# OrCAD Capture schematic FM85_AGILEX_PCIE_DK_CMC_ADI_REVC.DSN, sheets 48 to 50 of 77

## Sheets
48 LEDs, PushButton And IOEXP: size B
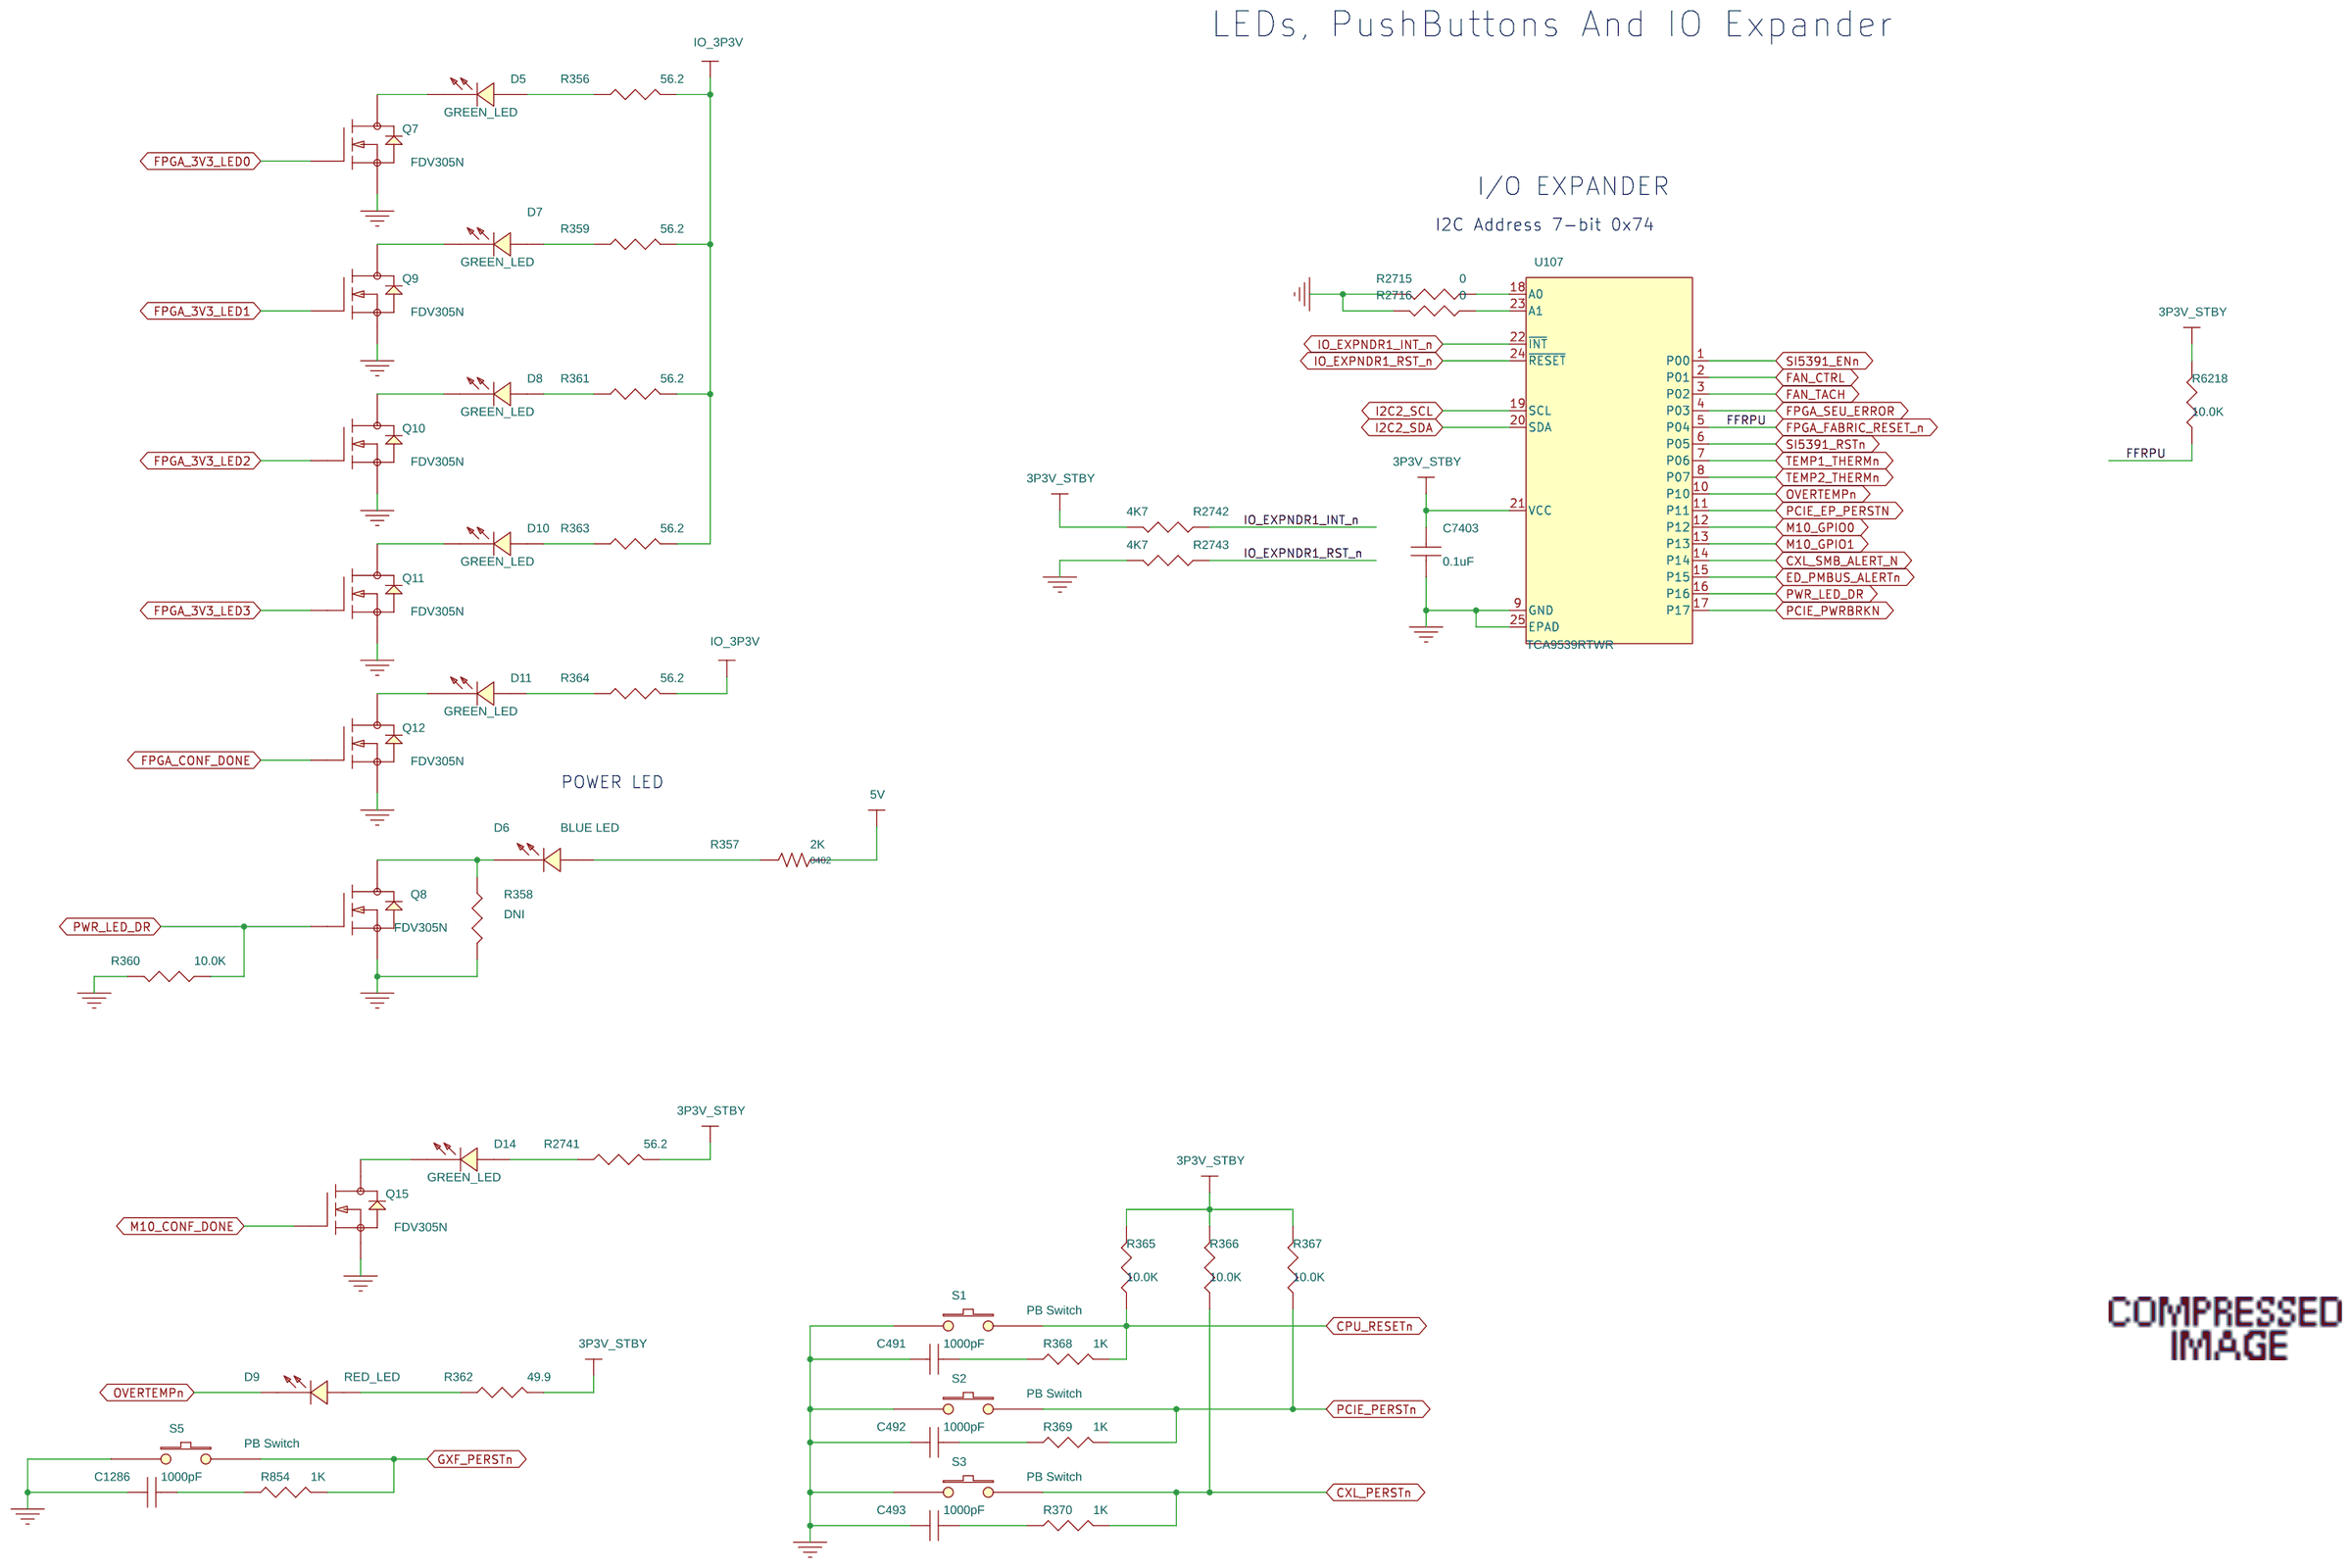
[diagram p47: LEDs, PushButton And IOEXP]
49 System MAX10 1: size B
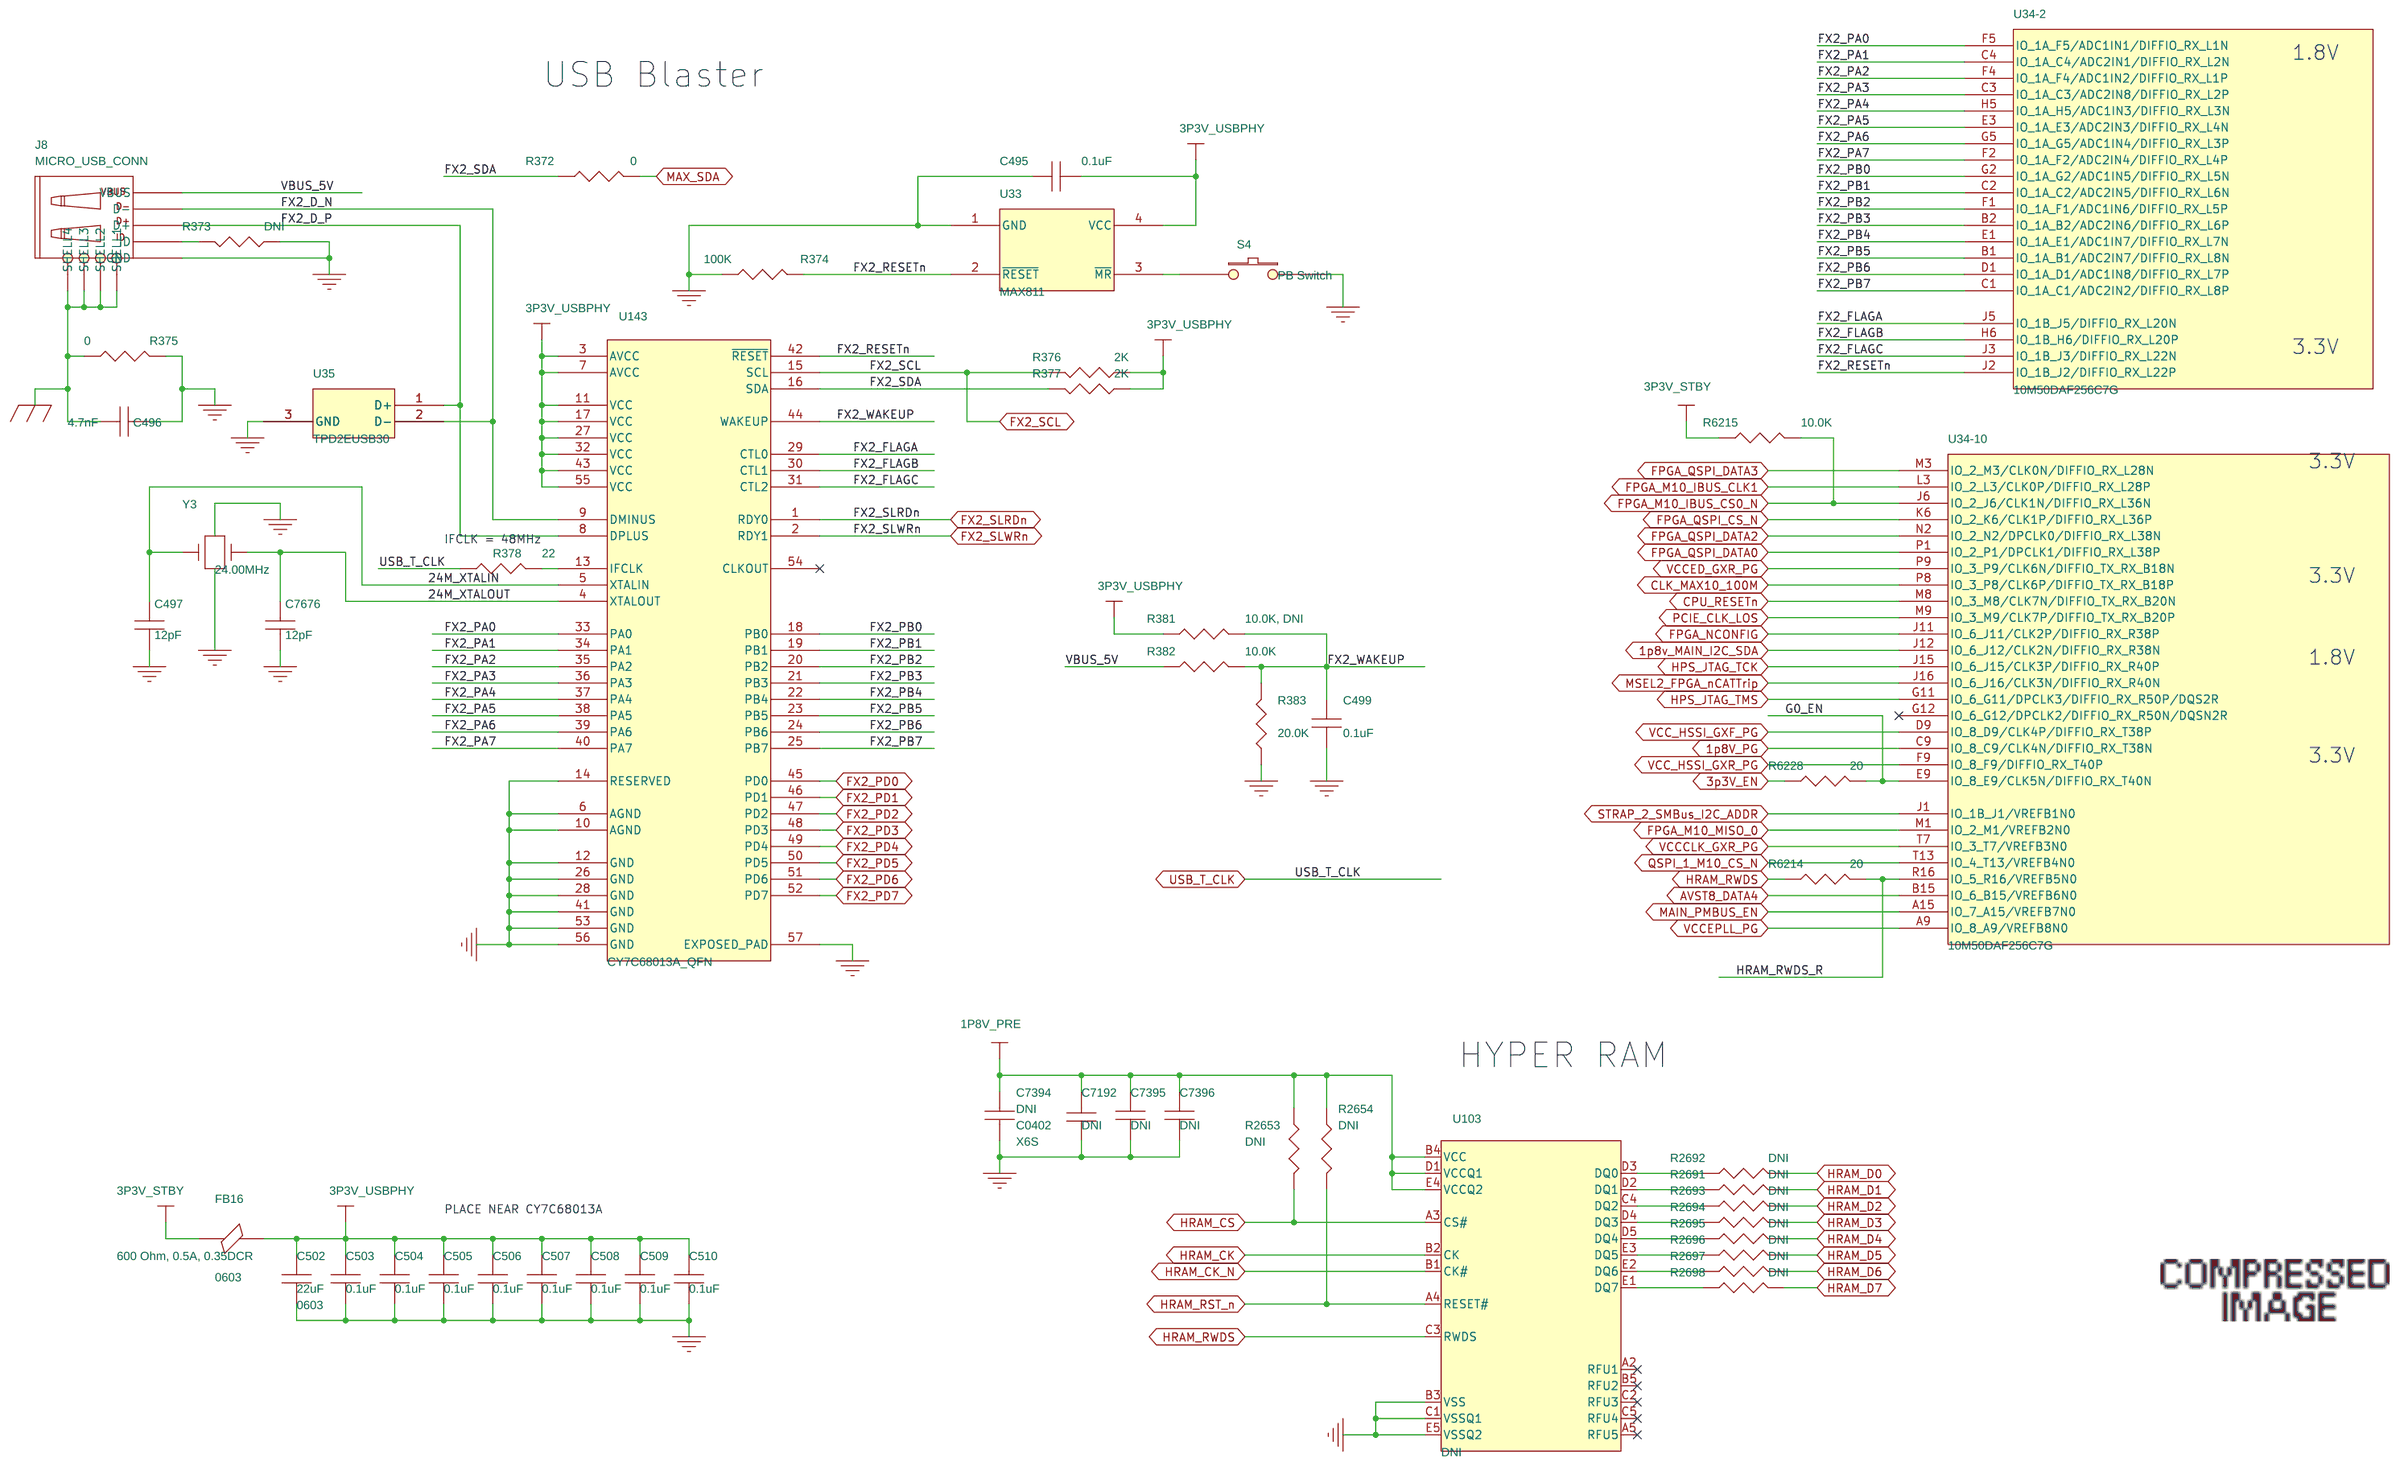
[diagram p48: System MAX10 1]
50 System MAX10 2: size B
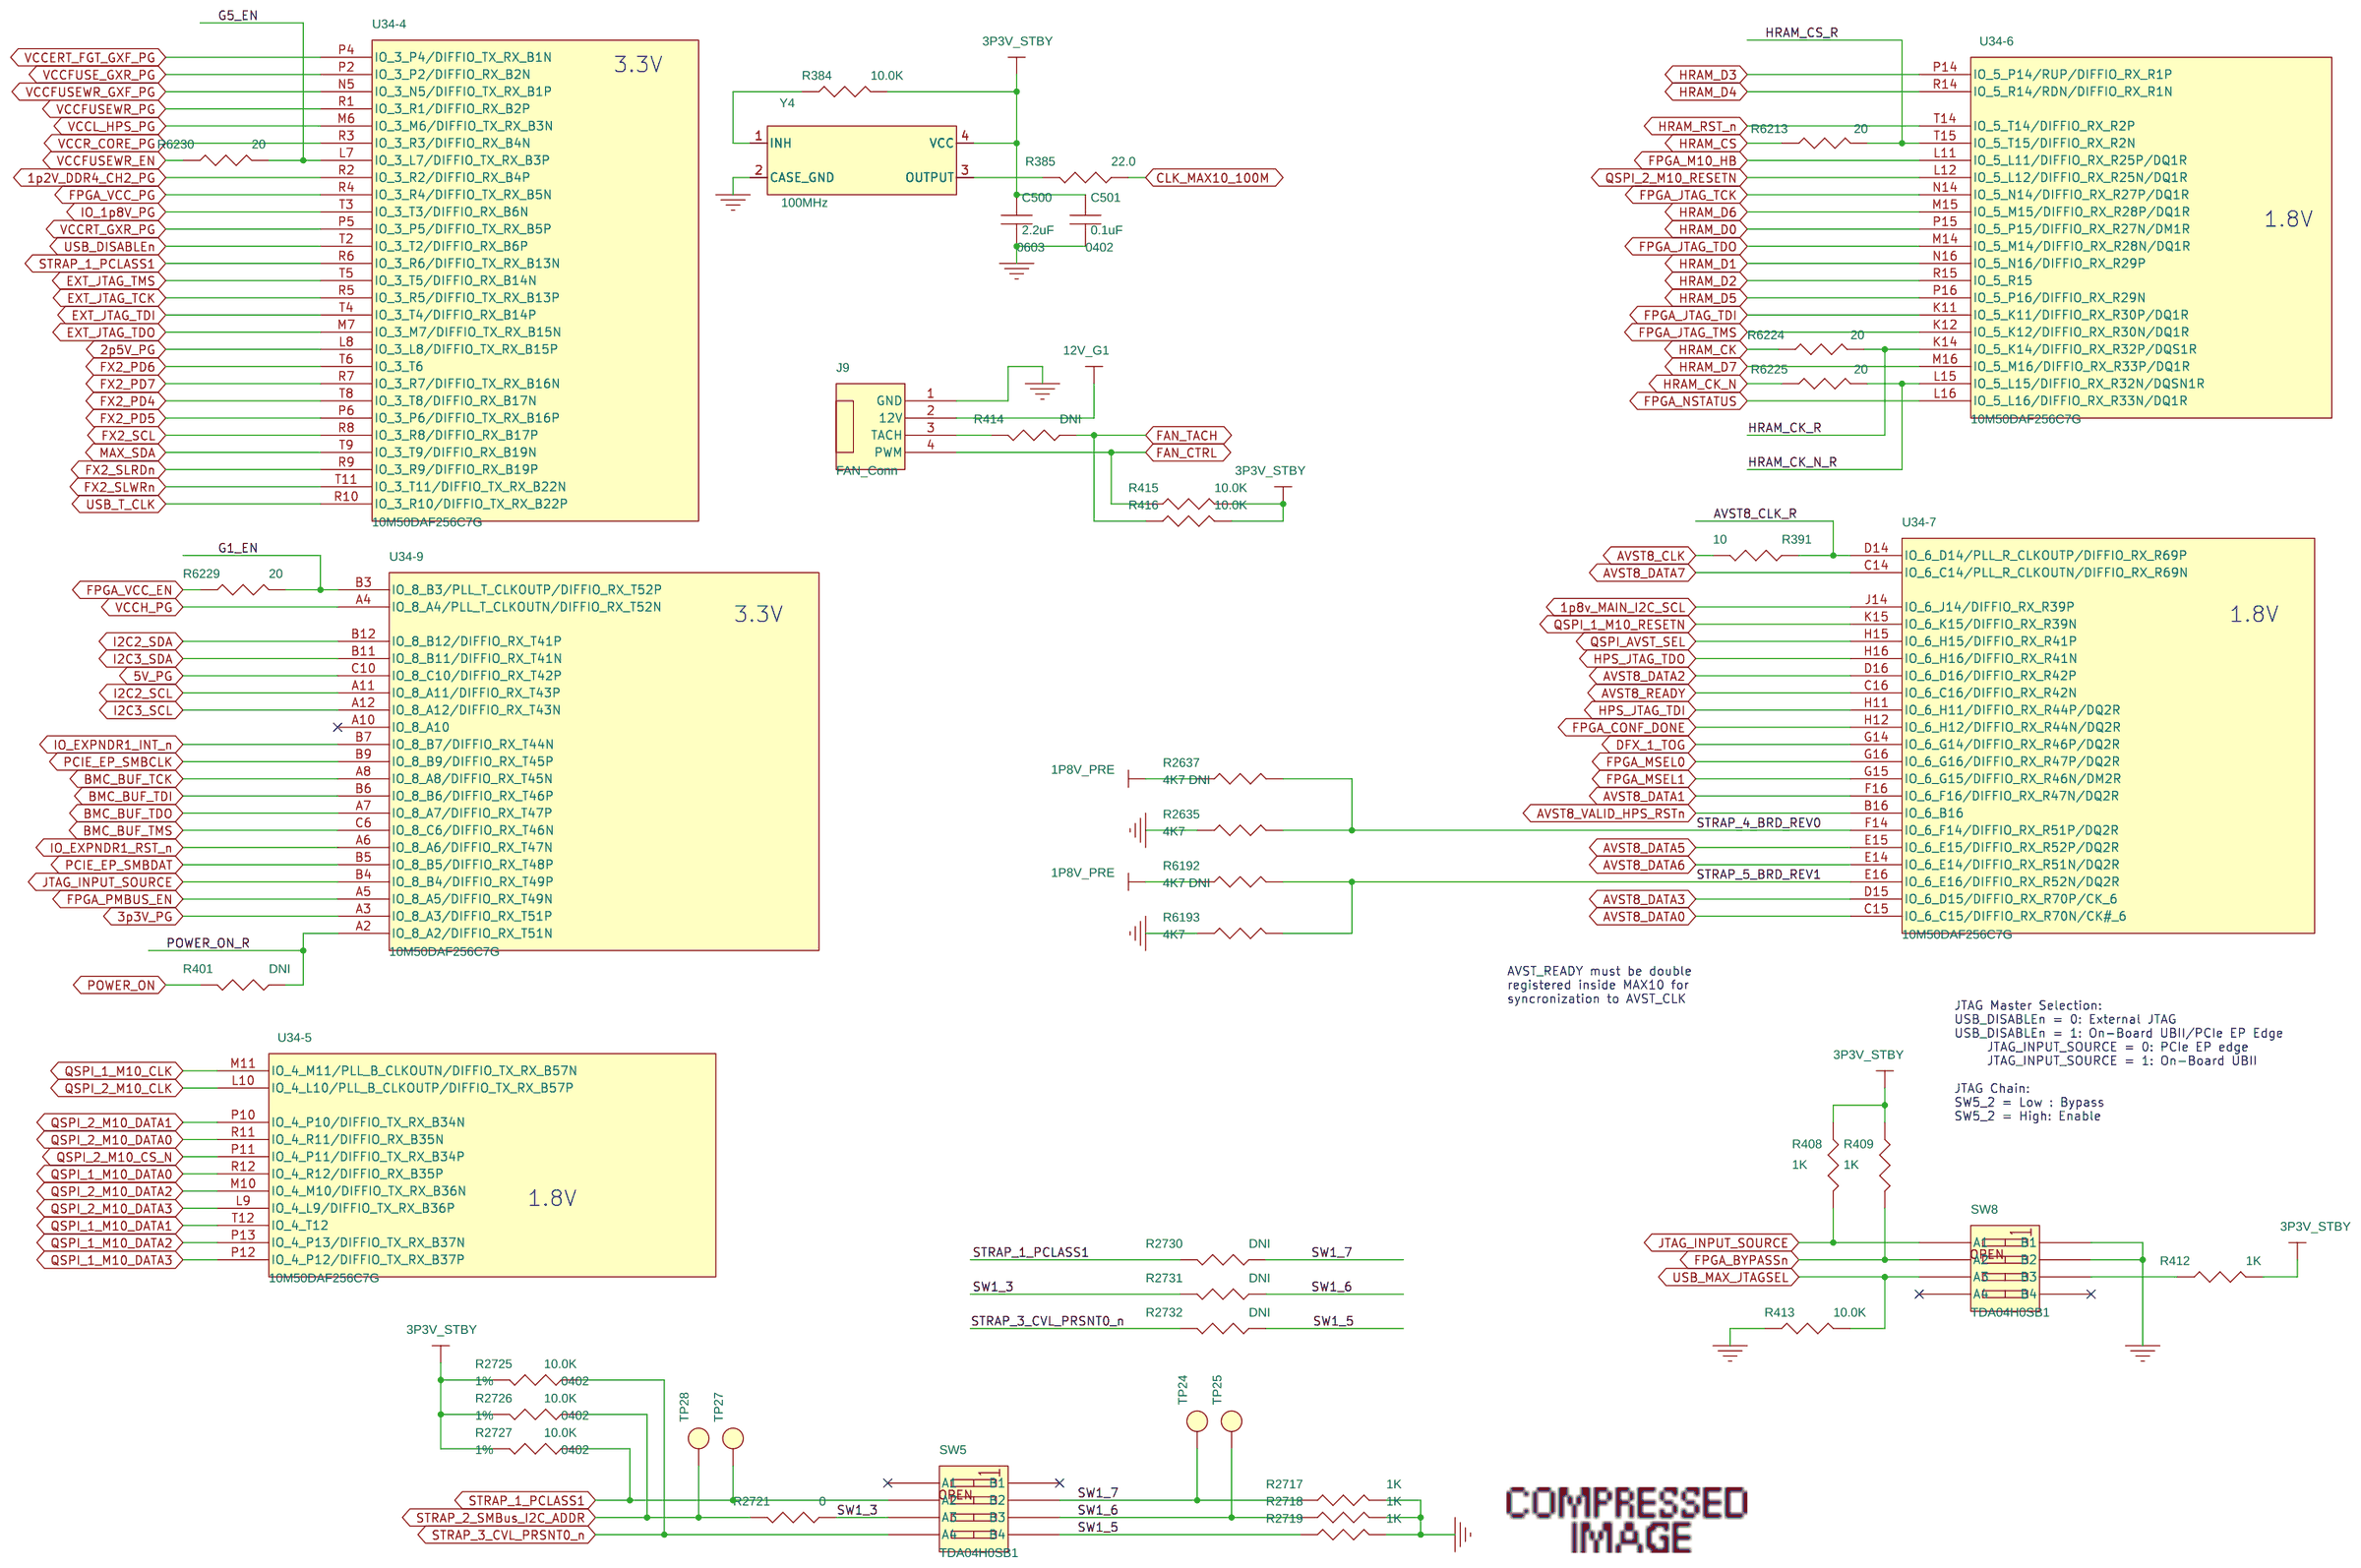
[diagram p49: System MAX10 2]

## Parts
sheet LEDs, PushButton And IOEXP
C491  1000pF  [0402]
C492  1000pF  [0402]
C493  1000pF  [0402]
C1286  1000pF  [0402]
C7403  0.1uF  [0402]
D5  GREEN_LED  [LED_0603]
D6  BLUE LED  [LED_0603]
D7  GREEN_LED  [LED_0603]
D8  GREEN_LED  [LED_0603]
D9  RED_LED  [LED_0603]
D10  GREEN_LED  [LED_0603]
D11  GREEN_LED  [LED_0603]
D14  GREEN_LED  [LED_0603]
Q7  FDV305N  [SOT23]
Q8  FDV305N  [SOT23]
Q9  FDV305N  [SOT23]
Q10  FDV305N  [SOT23]
Q11  FDV305N  [SOT23]
Q12  FDV305N  [SOT23]
Q15  FDV305N  [SOT23]
R356  56.2  [0402]
R357  2K  [0402]
R358  DNI  [0402]
R359  56.2  [0402]
R360  10.0K  [0402]
R361  56.2  [0402]
R362  49.9  [0402]
R363  56.2  [0402]
R364  56.2  [0402]
R365  10.0K  [0402]
R366  10.0K  [0402]
R367  10.0K  [0402]
R368  1K  [0402]
R369  1K  [0402]
R370  1K  [0402]
R854  1K  [0402]
R2715  0  [0402]
R2716  0  [0402]
R2741  56.2  [0402]
R2742  4K7  [0201]
R2743  4K7  [0201]
R6218  10.0K  [0402]
S1  PB Switch  [WURTH_6X3P5_TACT_SWITCH]
S2  PB Switch  [WURTH_6X3P5_TACT_SWITCH]
S3  PB Switch  [WURTH_6X3P5_TACT_SWITCH]
S5  PB Switch  [WURTH_6X3P5_TACT_SWITCH]
U107  TCA9539RTWR  [qfn50p410x410x80-25-cust]
sheet System MAX10 1
C495  0.1uF  [0402]
C496  4.7nF  [0402]
C497  12pF  [0402]
C499  0.1uF  [0402]
C502  22uF  [0603]
C503  0.1uF  [0402]
C504  0.1uF  [0402]
C505  0.1uF  [0402]
C506  0.1uF  [0402]
C507  0.1uF  [0402]
C508  0.1uF  [0402]
C509  0.1uF  [0402]
C510  0.1uF  [0402]
C7192  DNI  [C0402]
C7394  DNI  [C0402]
C7395  DNI  [C0402]
C7396  DNI  [C0402]
C7676  12pF  [0402]
FB16  600 Ohm, 0.5A, 0.35DCR  [0603]
J8  MICRO_USB_CONN  [molex-micro-usb-47589-001]
R372  0  [0402]
R373  DNI  [0402]
R374  100K  [0402]
R375  0  [0402]
R376  2K  [0402]
R377  2K  [0402]
R378  22  [0402]
R381  10.0K, DNI  [0402]
R382  10.0K  [0402]
R383  20.0K  [0402]
R2653  DNI  [0201]
R2654  DNI  [0201]
R2691  DNI  [0201]
R2692  DNI  [0201]
R2693  DNI  [0201]
R2694  DNI  [0201]
R2695  DNI  [0201]
R2696  DNI  [0201]
R2697  DNI  [0201]
R2698  DNI  [0201]
R6214  20  [0402]
R6215  10.0K  [0402]
R6228  20  [0402]
S4  PB Switch  [WURTH_6X3P5_TACT_SWITCH]
U33  MAX811  [SOT-143]
U35  TPD2EUSB30  [DRT]
U103  DNI  [TFBGA24]
U143  CY7C68013A_QFN  [QFN56]
Y3  24.00MHz  [XTAL_FA-128]
sheet System MAX10 2
C500  2.2uF  [0603]
C501  0.1uF  [0402]
J9  FAN_Conn  [Molex_0470533000]
R384  10.0K  [0402]
R385  22.0  [0402]
R391  10  [0402]
R401  DNI  [0402]
R408  1K  [0402]
R409  1K  [0402]
R412  1K  [0402]
R413  10.0K  [0402]
R414  DNI  [0402]
R415  10.0K  [0402]
R416  10.0K  [0402]
R2635  4K7  [0201]
R2637  4K7 DNI  [0201]
R2717  1K  [0402]
R2718  1K  [0402]
R2719  1K  [0402]
R2721  0  [0402]
R2725  10.0K  [0402]
R2726  10.0K  [0402]
R2727  10.0K  [0402]
R2730  DNI  [0402]
R2731  DNI  [0402]
R2732  DNI  [0402]
R6192  4K7 DNI  [0201]
R6193  4K7  [0201]
R6213  20  [0402]
R6224  20  [0402]
R6225  20  [0402]
R6229  20  [0402]
R6230  20  [0402]
SW5  TDA04H0SB1  [DIPSWITCH_SMT_QUAD]
SW8  TDA04H0SB1  [DIPSWITCH_SMT_QUAD]
TP24  TESTPOINT  [30MIL_TP]
TP25  TESTPOINT  [30MIL_TP]
TP27  TESTPOINT  [30MIL_TP]
TP28  TESTPOINT  [30MIL_TP]
Y4  100MHz  [XTAL_KC2520Z]
sheet System MAX10 3
U34  10M50DAF256C7G  [256FBGA]  (sections -1,-10,-11,-12,-2,-3,-4,-5,-6,-7,-8,-9)

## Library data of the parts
C491-C493 C1286 = CAP: CAPC,X7R,0402,1000.000PF,50.000V,+/- 10%; Dielectric: X7R; Item Num: A36096-004; LIFECYCLE_PHASE: Active; Lead Free Status: Lead Free; Manufacturer: Yageo; Manufacturer Part Num: CC0402KRX7R9BB102; Num Pins: 2; Part Class: CAPACITORS; RATED_VOLTAGE: 50V; RoHS Compliant: RoHS Compliant; Tolerance: 10%
C7403 = CAP: CAPC,  X7R, 0402, 0.1uF, 25V, ±20%; Item Num: K13660-001; LIFECYCLE_PHASE: Active; Lead Free Status: Lead Free; MFR_LIFECYCLE: Active; Manufacturer: Murata; Manufacturer Part Num: GRM155R71E104KE14D; Num Pins: 2; PART_SUBCLASS: CAPACITORS; Part Class: CAPACITORS; RATED_VOLTAGE: 25V; RoHS Compliant: RoHS Compliant; Tolerance: +80%/-20%
D5 D7 D8 D10 D11 D14 = LED_WURTH: LED - BRIGHT GREEN, VF=2V, IF=0.03A, 0603; Item Num: K15375-001; LIFECYCLE_PHASE: Active; Lead Free Status: Lead Free; Manufacturer: Wurth Electroniks; Manufacturer Part Num: 150060VS75000; Num Pins: 2; PART_SUBCLASS: LEDS; Part Class: LEDS; RoHS Compliant: RoHS Compliant
D6 = LED_0: LED - BLUE, VF = 3.2V, IF = 0.03A, 0603; Item Num: K15378-001; Lead Free Status: No; Manufacturer: Wurth Elektronik; Manufacturer Part Num: 150060BS75000
D9 = LED_WURTH: LED -SUPER RED, VF=1.9V, IF=0.03A, 0603; Item Num: K15376-001; LIFECYCLE_PHASE: Active; Lead Free Status: Lead Free; Manufacturer: Wurth Electroniks; Manufacturer Part Num: 150060SS75000; Num Pins: 2; PART_SUBCLASS: LEDS; Part Class: LEDS; RoHS Compliant: RoHS Compliant
Q7 Q9-Q12 Q15 = PWRMOSFET_EN_GSD_0: IC, MOSFET, N-Channel, 20V; Item Num: K21465-001; Manufacturer: Fairchild; Manufacturer Part Num: FDV305N_NL
Q8 = PWRMOSFET_EN_GSD_0: IC, MOSFET, N-Channel, 20V; Item Num: K21465-001; Manufacturer: Fairchild Semiconductor
R356 R359 R361 R363 R364 R2741 = RESISTOR_0: RES,56.2 OHMS,1.0%,1/16W,0402; Item Num: K16543-001; Lead Free Status: No; Manufacturer: Panasonic; Manufacturer Part Num: ERJ-2RKF56R2X; Num Pins: 2; Part Class: RESISTORS; Price: 0; RoHS Compliant: Yes
R357 = Resistor,_0402: RES,2.00K OHMS,1.0%,1/16W,0402; Agile Part Number: P02-17656R; Item Num: J43524-001; Manufacturer: Panasonic; Manufacturer Part Num: ERJ-2RKF2001X; Part Number: RMCF0603FT2K00; Power: 1/10W; TOLERANCE: ±1%
R358 = RESISTOR: RES ZERO OHM 1/16W 5% 0402 SMD; Item Num: J43364-001; Lead Free Status: No; Manufacturer: Panasonic; Manufacturer Part Num: ERJ-2GE0R00X; Num Pins: 2; Part Class: Resistors; Price: 0; RoHS Compliant: Yes
R360 R365-R367 R413 R415 R416 R6218 = RESISTOR: RES,10.0K OHMS,1.0%,1/16W, 0402; AGILE_LINK: http://sj-agile9app/Agile/PLMServlet?action=OpenEmailObject&classid=10000&objid=146548997; Item Num: K28115-001; LIFECYCLE_PHASE: Active; Lead Free Status: No; MFR_LIFECYCLE: Active; Manufacturer: Panasonic; Manufacturer Part Num: ERJ-2RKF1002X; Num Pins: 2; PART_SUBCLASS: RESISTORS; POWER: 1/16W; RoHS Compliant: Yes; TOLERANCE: +/-1%
R362 = RESISTOR: RES, 49.9 OHMS, 1%, 1/16W, 0402; Item Num: K16545-001; Lead Free Status: Yes; Manufacturer: NIC Components Corp.; Manufacturer Part Num: NRC04F49R9TRF; Num Pins: 2; Part Class: Resistors; Price: 0
R368-R370 R408 R409 R412 R854 R2717-R2719 = RESISTOR: RES,1.00K OHMS,1.0%,1/16W,0402; Item Num: G60609-021; Lead Free Status: No; Manufacturer: Panasonic; Manufacturer Part Num: ERJ-2RKF1001X; Num Pins: 2; Part Class: Resistors
R2715 R2716 R2721 = RESISTOR: RES ZERO OHM 1/16W 5% 0402 SMD; Agile IPN: P02-14020R; Altera Part No.: P02-14020R; Item Num: H30887-001; Lead Free Status: No; Manufacturer: Panasonic; Manufacturer Part Num: ERJ-2GE0R00X; Num Pins: 2; Part Class: RESISTORS; RoHS Compliant: Yes; Tolerance: 5%
R2653 R2742 R2743 = RES_VERT_HORIZ: RES-4K7-0201-1%-1/20W; Function: Resistor; Item Num: C48657-037; Lifecycle: Production; Manufacturer: YAGEO; Manufacturer Part Num: RC0201FR-074K7L; Part Type: Resistor; Part_Number: ERS000076; Tolerance: 1%; Wattage: 1/20W
S1-S5 = TS-A02SA-2-S100_0: SWITCH - PUSH BUTTON 6.0X3.5MM SND; Device: S7; Item Num: J43364-001; Lead Free Status: Yes; Manufacturer: Wurth Elektroniks; Manufacturer Part Num: 434121043816; Num Pins: 2; Part Class: Switches; RoHS Compliant: Yes
U107 = TCA9539RTWR: Item Num: M76619-001
C495 = CAP: CAPC,  X7R, 0402, 0.1uF, 25V, ±20%; Dielectric: Y5V; Item Num: K13660-001; LIFECYCLE_PHASE: Active; Lead Free Status: Lead Free; MFR_LIFECYCLE: Active; Manufacturer: Murata; Manufacturer Part Num: GRM155R71E104KE14D; Num Pins: 2; PART_SUBCLASS: CAPACITORS; Part Class: CAPACITORS; RATED_VOLTAGE: 25V; RoHS Compliant: RoHS Compliant; TOLERANCE: +80%/-20%
C496 = CAP: CAP - CER 4700PF 50V 10% X7R 0402; AGILE_LINK: http://sj-agile9app/Agile/PLMServlet?action=OpenEmailObject&classid=10000&objid=215384813; Item Num: A36096-066; LIFECYCLE_PHASE: Active; Lead Free Status: Lead Free; MFR_LIFECYCLE: Active; Manufacturer: Murata; Manufacturer Part Num: GRM155R71H472KA01D; Num Pins: 2; PACKAGING: Tape & Reel (TR); PART_SUBCLASS: CAPACITORS; RATED_VOLTAGE: 50V; RoHS Compliant: RoHS Compliant; Supplier Part Num: GRM155R71H472KA01D; Tolerance: +/-10%
C497 C7676 = CAP: CAP - 12PF, 50V, +/-5%, CERAMIC, 0402 SMD; AGILE_LINK: http://sj-agile9app/Agile/PLMServlet?action=OpenEmailObject&classid=10000&objid=257385742; Item Num: A36095-043; LIFECYCLE_PHASE: Active; Lead Free Status: Lead Free; MFR_LIFECYCLE: Active; Manufacturer: Murata; Manufacturer Part Num: GRM1555C1H120JA01F; Num Pins: 2; PART_SUBCLASS: CAPACITORS; RATED_VOLTAGE: 50V; RoHS Compliant: RoHS Compliant; TOLERANCE: +/-5%
C499 C503-C510 = CAP: CAPC,  X7R, 0402, 0.1uF, 25V, ±20%; AGILE_LINK: http://sj-agile9app/Agile/PLMServlet?action=OpenEmailObject&classid=10000&objid=213459527; Item Num: K13660-001; LIFECYCLE_PHASE: Active; Lead Free Status: Lead Free; MFR_LIFECYCLE: Active; Manufacturer: Murata; Manufacturer Part Num: GRM155R71E104KE14D; Num Pins: 2; PART_SUBCLASS: CAPACITORS; Part Class: CAPACITORS; RATED_VOLTAGE: 25V; RoHS Compliant: RoHS Compliant; TOLERANCE: +80%/-20%
C502 = CAP: CAP CER 22UF 6.3V X6S 0603; AGILE_LINK: http://sj-agile9app/Agile/PLMServlet?action=OpenEmailObject&classid=10000&objid=257560276; Item Num: H63299-001; LIFECYCLE_PHASE: Active; Lead Free Status: Lead Free; MFR_LIFECYCLE: Active; Manufacturer: Murata; Manufacturer Part Num: GRM188C80J226ME15D; Num Pins: 2; PART_SUBCLASS: CAPACITORS; RATED_VOLTAGE: 6.3V; RoHS Compliant: RoHS Compliant; TOLERANCE: 20%; Temperature Coefficient: X6S
C7192 C7395 C7396 = CAP: CAP-100n-0402-10%-X7R-25V; ALT_SYMBOLS: 0402CIR_M; CAPACITANCE: 0.1uF; Dielectric: X5R; Item Num: C83410-027; LIFECYCLE_PHASE: Active; Lead Free Status: Lead Free; Lifecycle: Pilot; Manufacturer: TDK Electronics; Manufacturer Part Num: C1005X7R1E104M; Num Pins: 2; Package: 0402; Part Class: CAPACITORS; Part Type: Capacitor; Part_Number: ECC000114; Price: 0.07; RoHS Compliant: RoHS Compliant; Tolerance: 10%; Voltage (V): 25V
C7394 = CAP: CAP-4u7-0402-20%-X6S-6.3V; ALT_SYMBOLS: 0402CIR_M; Item Num: D97712-014; Lifecycle: Pilot; Manufacturer: Murata; Manufacturer Part Num: GRM155C80J475MEAA; Package: 0402; Part Type: Capacitor; Part_Number: ECC000170; Temperature (Celcius): X6S -55- +105; Temperature Coefficient: X6S; Tolerance: 10%; Voltage: 6.3V; Voltage (V): 6.3V
FB16 = BEAD_FERRITE_SM: FERRITE BEAD 600 OHM, 0.5A, 0.35 DCR, 0603 1LN; Item Num: G73133-001; LIFECYCLE_PHASE: Active; MFR_LIFECYCLE: Active; Manufacturer: Murata; Manufacturer Part Num: BLM18EG601SN1D; Num Pins: 2; Part Class: Inductors; RoHS Compliant: Yes
J8 = MICRO_USB_CONN: RECEPTACLE, USB 3.0, MICRO B, R/A; Item Num: G68794-001; Lead Free Status: Yes; MFR_LIFECYCLE: Active; Manufacturer: Molex; Manufacturer Part Num: 47589-0001; Num Pins: 9; Part Class: Connectors; RoHS Compliant: Yes
R372 R375 = RESISTOR: RES ZERO OHM 1/16W 5% 0402 SMD; Altera Part No.: P02-14020R; Item Num: H30887-001; Lead Free Status: No; Manufacturer: Panasonic; Manufacturer Part Num: ERJ-2GE0R00X; Num Pins: 2; Part Class: RESISTORS; RoHS Compliant: Yes; Tolerance: 5%
R373 R2730-R2732 = RES_0_OHM_5%_1_16W_0402_SMD: Item Num: H30887-001
R374 = RESISTOR: RES, 100K OHMS, 1.0%, 1/10W, 0402; Item Num: E86804-001; Lead Free Status: No; Manufacturer: Panasonic; Manufacturer Part Num: ERJ-2RKF1003X; Num Pins: 2; Part Class: Resistors; Price: 0; RoHS Compliant: Yes
R376 R377 = RESISTOR: RES,2.00K OHMS,1.0%,1/16W,0402; Item Num: J43524-001; Lead Free Status: No; Manufacturer: Panasonic; Manufacturer Part Num: ERJ-2RKF2001X; Manufacturer's Part No.: ERJ-2RKF2001X; Num Pins: 2; Part Class: RESISTORS; Price: 0; RoHS Compliant: Yes
R378 = RESISTOR: RES, 22 OHMS, 5%, 1/16W, 0402; AGILE_LINK: http://sj-agile9app/Agile/PLMServlet?action=OpenEmailObject&classid=10000&objid=218074840; Item Num: K15613-001; LIFECYCLE_PHASE: Active; MFR_LIFECYCLE: Active; Manufacturer: NIC Components Corp.; Manufacturer Part Num: NRC04J220TRF; Num Pins: 2; PART_SUBCLASS: RESISTORS; POWER: 1/16W; RoHS Compliant: RoHS Compliant; TOLERANCE: +/-5%
R381 R382 R6215 = RESISTOR: RES,10.0K OHMS,1.0%,1/16W, 0402; AGILE_LINK: http://sj-agile9app/Agile/PLMServlet?action=OpenEmailObject&classid=10000&objid=146548997; Item Num: K28115-001; LIFECYCLE_PHASE: Active; Lead Free Status: No; MFR_LIFECYCLE: Active; Manufacturer: Panasonic; Manufacturer Part Num: ERJ-2RKF1002X; Num Pins: 2; PART_SUBCLASS: RESISTORS; POWER: 1/16W; RESISTANCE: 10K; RoHS Compliant: Yes; TOLERANCE: +/-1%
R383 = RESISTOR: RES 20.0K OHM 1/16W 1% 0402 SMD; Item Num: A78608-001; Lead Free Status: Yes; Manufacturer: Panasonic; Manufacturer Part Num: ERJ-2RKF2002X; Num Pins: 2; Part Class: RESISTORS; RoHS Compliant: Yes
R2635 R2654 R6193 = RES_VERT_HORIZ: RES-4K7-0201-1%-1/20W; Function: Resistor; Item Num: C48657-037; Lifecycle: Production; Manufacturer: YAGEO; Manufacturer Part Num: RC0201FR-074K7L; Part Type: Resistor; Part_Number: ERS000076; Power (W): 1/20W; Tolerance: 1%; Wattage: 1/20W
R2691-R2698 = RES_VERT_HORIZ: RES-33R2-0201-1%-1/20W; Function: Resistor; Item Num: H36675-070; Lifecycle: Pilot; Manufacturer Part Num: RC0201FR-0733R2P; Part Type: Resistor; Part_Number: ERS000123; Power (W): 1/20W; Tolerance: 1%; Wattage: 1/20W
R6213 R6214 R6224 R6225 R6228-R6230 = RESISTOR: RES SMDRES D,0402,20.00 OHM,1.00%,1/16W; Item Num: A93548-053; Lead Free Status: No; Manufacturer: Vishay; Manufacturer Part Num: CRCW040220R0FKED; Num Pins: 2; Part Class: Resistors; TOLERANCE: 1%
U33 = MAX811: IC - MPU V-MONITOR 2.93V, RESET/POWER-ON RESET, SOT143-4; Item Num: D16587-001; Lead Free Status: Yes; Manufacturer: Maxim Integrated Products; Manufacturer Part Num: MAX811SEUS+T; Num Pins: 4; Part Class: ICs; RoHS Compliant: Yes
U35 = TPD2EUSB30: DIODE - FULL SPEED USB ESD SOLUTION, 2CH, SOT3; Item Num: K12736-001; Lead Free Status: Yes; MFR_LIFECYCLE: Active; Manufacturer: Texas Instruments; Manufacturer Part Num: TPD2EUSB30DRxx; Num Pins: 3; Part Class: ICS; RoHS Compliant: Yes
U103 = W956D8MBYA6I: HyperRAM Memory IC 64Mb (8M x 8) HyperBus 166 MHz 36 ns 24-TFBGA (6x8); Item Num: M48812-002; Part_Number: ICM000273
U143 = CY7C68013A_56QFN: IC - EZ-USB FX2LP Microcontroller 400KHz, 56-QFN, 3.3V; Item Num: K33816-001; Lead Free Status: Yes; Manufacturer: Cypress; Manufacturer Part Num: CY7C68013A-56LTXCx; Num Pins: 57; Part Class: ICs; RoHS Compliant: Yes
Y3 = CRYSTAL_SM_13: CRYSTAL - MINI XTL, 24.00 MHZ, +/-50PPM, +/-30PPM-20~75C, 12PF, 2.0mm x 1.6mm SMD; Item Num: K15535-001; Lead Free Status: Yes; MFR_LIFECYCLE: Active; Manufacturer: Epson Toyocom; Manufacturer Part Num: FA-128 24.0000MB-W; Num Pins: 4; RoHS Compliant: Yes
C500 = CAP: CAP, CERAMIC, 2.2UF, 10%, 10VDC, X5R, 0603; AGILE_LINK: http://sj-agile9app/Agile/PLMServlet?action=OpenEmailObject&classid=10000&objid=256999866; Agile IPN: P03-15213R; Dielectric: X5R; Item Num: K13568-001; LIFECYCLE_PHASE: Active; MFR_LIFECYCLE: Active; Manufacturer: Murata; Manufacturer Part Num: GRM188R61A225KE34x; Num Pins: 2; PART_SUBCLASS: CAPACITORS; RATED_VOLTAGE: 10V; RoHS Compliant: RoHS Compliant; Supplier Part Num: 490-1545-1-ND; TOLERANCE: +/-10%
C501 = CAP: CAPC,  X7R, 0402, 0.1uF, 25V, ±20%; AGILE_LINK: http://sj-agile9app/Agile/PLMServlet?action=OpenEmailObject&classid=10000&objid=213459527; Dielectric: Y5V; Item Num: K13660-001; LIFECYCLE_PHASE: Active; Lead Free Status: Lead Free; MFR_LIFECYCLE: Active; Manufacturer: Murata; Manufacturer Part Num: GRM155R71E104KE14D; Num Pins: 2; PART_SUBCLASS: CAPACITORS; Part Class: CAPACITORS; RATED_VOLTAGE: 25V; RoHS Compliant: RoHS Compliant; TOLERANCE: +80%/-20%
J9 = FAN_Conn_0: 4 POSITIONS HEADER, UNSHROUDED CONNECTOR 0.100" (2.54MM) THROUGH HOLE TIN; Item Num: K21517-001; Manufacturer: Molex; Manufacturer Name: Molex; Manufacturer Part Num: 0470533000
R384 = RESISTOR: RES,10.0K OHMS,1.0%,1/16W, 0402; AGILE_LINK: http://sj-agile9app/Agile/PLMServlet?action=OpenEmailObject&classid=10000&objid=146548997; Agile IPN: P02-11364R; Item Num: K28115-001; LIFECYCLE_PHASE: Active; Lead Free Status: No; MFR_LIFECYCLE: Active; Manufacturer: Panasonic; Manufacturer Part Num: ERJ-2RKF1002X; Num Pins: 2; PART_SUBCLASS: RESISTORS; POWER: 1/16W; RESISTANCE: 10K; RoHS Compliant: Yes; TOLERANCE: +/-1%
R385 = RESISTOR: RES - 22.0 OHM, 1/16W, 1%, 0402 SMD; Agile IPN: P02-16269R; Item Num: K15746-001; Lead Free Status: Yes; Manufacturer: Panasonic; Manufacturer Part Num: ERJ-2RKF22R0X; Num Pins: 2; Part Class: Resistors; Price: 0
R391 = RESISTOR: RES, 10 OHM, 1%, 1/16W, 0402; AGILE_LINK: http://sj-agile9app/Agile/PLMServlet?action=OpenEmailObject&classid=10000&objid=146932246; Agile IPN: P02-16268R; Item Num: A80345-001; LIFECYCLE_PHASE: Active; MFR_LIFECYCLE: Active; Manufacturer: Panasonic; Manufacturer Part Num: ERJ-2RKF10R0X; Num Pins: 2; PART_SUBCLASS: RESISTORS; POWER: 1/16W; RoHS Compliant: RoHS Compliant; TOLERANCE: +/-1%
R401 R414 = RESISTOR: RES ZERO OHM 1/16W 5% 0402 SMD; Agile IPN: P02-14020R; Altera Part No.: P02-14020R; Item Num: H30887-001; Lead Free Status: No; Manufacturer: Panasonic; Manufacturer Part Num: ERJ-2GE0R00X; Num Pins: 2; Part Class: RESISTORS; Price: 0; RoHS Compliant: Yes; Tolerance: 5%
R2637 R6192 = RES_VERT_HORIZ: RES-4K7-0201-1%-1/20W; Function: Resistor; Item Num: C48657-037; Lifecycle: Production; Manufacturer: YAGEO; Manufacturer Part Num: RC0201FR-074K7L; Part Type: Resistor; Part_Number: ERS000076; ROOM: DNI; Tolerance: 1%; Wattage: 1/20W
R2725-R2727 = RESISTOR: RES,10.0K OHMS,1.0%,1/16W, 0402; AGILE_LINK: http://sj-agile9app/Agile/PLMServlet?action=OpenEmailObject&classid=10000&objid=146548997; Item Num: K28115-001; LIFECYCLE_PHASE: Active; Lead Free Status: No; MFR_LIFECYCLE: Active; Manufacturer: Panasonic; Manufacturer Part Num: ERJ-2RKF1002X; Num Pins: 2; PART_SUBCLASS: RESISTORS; POWER: 1/16W; RESISTANCE: 10K; RoHS Compliant: Yes; TOLERANCE: 1%
SW5 SW8 = SPST4: SWITCHES - 4 POS, 8 PIN, Ultra-mini SMT Half-pitch Slider DIP Switch; Item Num: K15518-001; Lead Free Status: Yes; Manufacturer: C & K Components/ITT Industries; Num Pins: 8; Part Class: Switches; Price: 0; RoHS Compliant: Yes; Supplier: 8
TP24 TP25 TP27 TP28 = TP,_0.016_,_Thru_Hole
Y4 = KC2520Z100.000C15XXK: Item Num: M85602-001
U34 = 10M50DA_F256: IC FPGA 178 I/O 256FBGA; Agile IPN: P01-18272R; Item Num: 973682; Manufacturer: Intel

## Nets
5V: R357.2 ; also on sheet 57 59 65 68 73
5V_PG: U34.C10(IO_8_C10/DIFFIO_RX_T42P) ; also on sheet 57
12V_G1: J9.2(12V) ; also on sheet 19 20 53 54 55 56
GND: C491.1 C492.1 C493.1 C495.1 C496.2 C497.2 C499.2 C500.2 C501.2 C502.2 C503.2 C504.2 C505.2 C506.2 C507.2 C508.2 C509.2 C510.2 C1286.1 C7192.1 C7394.2 C7395.2 C7396.2 C7403.2 C7676.2 J8.5(GND) J9.1(GND) Q7.2(SOURCE) Q8.2(SOURCE) Q9.2(SOURCE) Q10.2(SOURCE) Q11.2(SOURCE) Q12.2(SOURCE) Q15.2(SOURCE) R358.1 R360.2 R373.1 R374.2 R375.2 R383.1 R413.1 R2635.1 R2715.1 R2716.1 R2717.1 R2718.1 R2719.1 R2743.2 R6193.1 S1.1 S2.1 S3.1 S4.2 S5.1 SW8.7(B2) SW8.8(B1) U33.1(GND) U35.3(GND) U103.B3(VSS) U103.C1(VSSQ1) U103.E5(VSSQ2) U107.9(GND) U107.25(EPAD) U143.6(AGND) U143.10(AGND) U143.12(GND) U143.14(RESERVED) U143.26(GND) U143.28(GND) U143.41(GND) U143.53(GND) U143.56(GND) U143.57(EXPOSED_PAD) Y3.2 Y3.4 Y4.2(CASE_GND) ; also on sheet 9 10 11 13 14 15 16 17 18 19 20 21 22 23 25 26 27 28 29 30 31 32 33 34 35 36 38 39 40 41 42 43 44 45 46 47 51 52 53 54 55 56 57 58 59 60 61 62 63 64 65 66 67 68 69 70 71 72 73 74 75 76 77
GND_CHS: C496.1 J8.6(SHELL1) J8.7(SHELL2) J8.8(SHELL3) J8.9(SHELL4) R375.1
VBUS_5V: J8.1(VBUS) R382.1
VCC_HSSI_GXF_PG: U34.D9(IO_8_D9/CLK4P/DIFFIO_RX_T38P) ; also on sheet 65
VCC_HSSI_GXR_PG: U34.F9(IO_8_F9/DIFFIO_RX_T40P) ; also on sheet 63
VCCCLK_GXR_PG: U34.T7(IO_3_T7/VREFB3N0) ; also on sheet 74
VCCED_GXR_PG: U34.P9(IO_3_P9/CLK6N/DIFFIO_TX_RX_B18N) ; also on sheet 60
VCCEPLL_PG: U34.A9(IO_8_A9/VREFB8N0) ; also on sheet 69
VCCERT_FGT_GXF_PG: U34.P4(IO_3_P4/DIFFIO_TX_RX_B1N) ; also on sheet 61
VCCFUSE_GXR_PG: U34.P2(IO_3_P2/DIFFIO_RX_B2N) ; also on sheet 74
VCCFUSEWR_EN: R6230.2 ; also on sheet 69
VCCFUSEWR_GXF_PG: U34.N5(IO_3_N5/DIFFIO_TX_RX_B1P) ; also on sheet 74
VCCFUSEWR_PG: U34.R1(IO_3_R1/DIFFIO_RX_B2P) ; also on sheet 69
VCCH_PG: U34.A4(IO_8_A4/PLL_T_CLKOUTN/DIFFIO_RX_T52N) ; also on sheet 64
VCCL_HPS_PG: U34.M6(IO_3_M6/DIFFIO_TX_RX_B3N) ; also on sheet 60
VCCR_CORE_PG: U34.R3(IO_3_R3/DIFFIO_RX_B4N) ; also on sheet 59
VCCRT_GXR_PG: U34.P5(IO_3_P5/DIFFIO_TX_RX_B5P) ; also on sheet 62
1p2V_DDR4_CH2_PG: U34.R2(IO_3_R2/DIFFIO_RX_B4P) ; also on sheet 71
1p8v_MAIN_I2C_SCL: U34.J14(IO_6_J14/DIFFIO_RX_R39P) ; also on sheet 36 77
1p8v_MAIN_I2C_SDA: U34.J12(IO_6_J12/CLK2N/DIFFIO_RX_R38N) ; also on sheet 36 77
1p8V_PG: U34.C9(IO_8_C9/CLK4N/DIFFIO_RX_T38N) ; also on sheet 66
1p8V_PRE: C7192.2 C7394.1 C7395.1 C7396.1 R2637.1 R2653.1 R2654.1 R6192.1 U103.B4(VCC) U103.D1(VCCQ1) U103.E4(VCCQ2) ; also on sheet 35 51 68
2p5V_PG: U34.L8(IO_3_L8/DIFFIO_TX_RX_B15P) ; also on sheet 73
3p3V_EN: R6228.2 ; also on sheet 58
3p3V_PG: U34.A3(IO_8_A3/DIFFIO_RX_T51P) ; also on sheet 58
3p3V_STBY: C500.1 C501.1 C7403.1 FB16.2 R362.2 R365.2 R366.2 R367.2 R384.2 R408.2 R409.2 R412.1 R415.2 R416.2 R2725.1 R2726.1 R2727.1 R2741.2 R2742.2 R6215.1 R6218.2 U107.21(VCC) Y4.4(VCC) ; also on sheet 30 44 51 52 53 57 77
3p3V_USBPHY: C495.2 C502.1 C503.1 C504.1 C505.1 C506.1 C507.1 C508.1 C509.1 C510.1 FB16.1 R376.2 R377.2 R381.1 U33.4(VCC) U143.3(AVCC) U143.7(AVCC) U143.11(VCC) U143.17(VCC) U143.27(VCC) U143.32(VCC) U143.43(VCC) U143.55(VCC)
24M_XTALIN: C497.1 U143.5(XTALIN) Y3.1
24M_XTALOUT: C7676.1 U143.4(XTALOUT) Y3.3
AVST8_CLK: R391.2 ; also on sheet 35
AVST8_CLK_R: R391.1 U34.D14(IO_6_D14/PLL_R_CLKOUTP/DIFFIO_RX_R69P)
AVST8_DATA0: U34.C15(IO_6_C15/DIFFIO_RX_R70N/CK#_6) ; also on sheet 35
AVST8_DATA1: U34.F16(IO_6_F16/DIFFIO_RX_R47N/DQ2R) ; also on sheet 35
AVST8_DATA2: U34.D16(IO_6_D16/DIFFIO_RX_R42P) ; also on sheet 35
AVST8_DATA3: U34.D15(IO_6_D15/DIFFIO_RX_R70P/CK_6) ; also on sheet 35
AVST8_DATA4: U34.B15(IO_6_B15/VREFB6N0) ; also on sheet 35
AVST8_DATA5: U34.E15(IO_6_E15/DIFFIO_RX_R52P/DQ2R) ; also on sheet 35
AVST8_DATA6: U34.E14(IO_6_E14/DIFFIO_RX_R51N/DQ2R) ; also on sheet 35
AVST8_DATA7: U34.C14(IO_6_C14/PLL_R_CLKOUTN/DIFFIO_RX_R69N) ; also on sheet 35
AVST8_READY: U34.C16(IO_6_C16/DIFFIO_RX_R42N) ; also on sheet 35
AVST8_VALID_HPS_RSTn: U34.B16(IO_6) ; also on sheet 35
BMC_BUF_TCK: U34.A8(IO_8_A8/DIFFIO_RX_T45N) ; also on sheet 52
BMC_BUF_TDI: U34.B6(IO_8_B6/DIFFIO_RX_T46P) ; also on sheet 52
BMC_BUF_TDO: U34.A7(IO_8_A7/DIFFIO_RX_T47P) ; also on sheet 52
BMC_BUF_TMS: U34.C6(IO_8_C6/DIFFIO_RX_T46N) ; also on sheet 52
CLK_MAX10_100M: R385.1 U34.P8(IO_3_P8/CLK6P/DIFFIO_TX_RX_B18P)
CPU_RESETn: R365.1 R368.1 S1.2 U34.M8(IO_3_M8/CLK7N/DIFFIO_TX_RX_B20N) ; also on sheet 52
CXL_PERSTn: R366.1 R370.1 S3.2 ; also on sheet 32 33 52
CXL_SMB_ALERT_N: U107.14(P14) ; also on sheet 32
DFX_1_TOG: U34.G14(IO_6_G14/DIFFIO_RX_R46P/DQ2R) ; also on sheet 28
ED_PMBUS_ALERTn: U107.15(P15) ; also on sheet 54
EXT_JTAG_TCK: U34.R5(IO_3_R5/DIFFIO_TX_RX_B13P) ; also on sheet 51
EXT_JTAG_TDI: U34.T4(IO_3_T4/DIFFIO_RX_B14P) ; also on sheet 51
EXT_JTAG_TDO: U34.M7(IO_3_M7/DIFFIO_TX_RX_B15N) ; also on sheet 51
EXT_JTAG_TMS: U34.T5(IO_3_T5/DIFFIO_RX_B14N) ; also on sheet 51
FAN_CTRL: J9.4(PWM) R415.1 U107.2(P01)
FAN_TACH: R414.2 R416.1 U107.3(P02)
FPGA_3V3_LED0: Q7.1(GATE) ; also on sheet 52
FPGA_3V3_LED1: Q9.1(GATE) ; also on sheet 52
FPGA_3V3_LED2: Q10.1(GATE) ; also on sheet 52
FPGA_3V3_LED3: Q11.1(GATE) ; also on sheet 52
FPGA_BYPASSn: R409.1 SW8.2(A2) ; also on sheet 51
FPGA_CONF_DONE: Q12.1(GATE) U34.H12(IO_6_H12/DIFFIO_RX_R44N/DQ2R) ; also on sheet 35
FPGA_FABRIC_RESET_n: R6218.1 U107.5(P04) ; also on sheet 52
FPGA_JTAG_TCK: U34.N14(IO_5_N14/DIFFIO_RX_R27P/DQ1R) ; also on sheet 35
FPGA_JTAG_TDI: U34.K11(IO_5_K11/DIFFIO_RX_R30P/DQ1R) ; also on sheet 35
FPGA_JTAG_TDO: U34.M14(IO_5_M14/DIFFIO_RX_R28N/DQ1R) ; also on sheet 35
FPGA_JTAG_TMS: U34.K12(IO_5_K12/DIFFIO_RX_R30N/DQ1R) ; also on sheet 35
FPGA_M10_HB: U34.L11(IO_5_L11/DIFFIO_RX_R25P/DQ1R) ; also on sheet 22
FPGA_M10_IBUS_CLK1: U34.L3(IO_2_L3/CLK0P/DIFFIO_RX_L28P) ; also on sheet 77
FPGA_M10_IBUS_CS0_N: R6215.2 U34.J6(IO_2_J6/CLK1N/DIFFIO_RX_L36N) ; also on sheet 77
FPGA_M10_MISO_0: U34.M1(IO_2_M1/VREFB2N0) ; also on sheet 77
FPGA_MSEL0: U34.G16(IO_6_G16/DIFFIO_RX_R47P/DQ2R) ; also on sheet 35
FPGA_MSEL1: U34.G15(IO_6_G15/DIFFIO_RX_R46N/DM2R) ; also on sheet 35
FPGA_NCONFIG: U34.J11(IO_6_J11/CLK2P/DIFFIO_RX_R38P) ; also on sheet 35
FPGA_NSTATUS: U34.L16(IO_5_L16/DIFFIO_RX_R33N/DQ1R) ; also on sheet 35
FPGA_PMBUS_EN: U34.A5(IO_8_A5/DIFFIO_RX_T49N) ; also on sheet 46
FPGA_QSPI_CS_N: U34.K6(IO_2_K6/CLK1P/DIFFIO_RX_L36P) ; also on sheet 52
FPGA_QSPI_DATA0: U34.P1(IO_2_P1/DPCLK1/DIFFIO_RX_L38P) ; also on sheet 52
FPGA_QSPI_DATA2: U34.N2(IO_2_N2/DPCLK0/DIFFIO_RX_L38N) ; also on sheet 52
FPGA_QSPI_DATA3: U34.M3(IO_2_M3/CLK0N/DIFFIO_RX_L28N) ; also on sheet 52
FPGA_SEU_ERROR: U107.4(P03) ; also on sheet 77
FPGA_VCC_EN: R6229.2 ; also on sheet 54
FPGA_VCC_PG: U34.R4(IO_3_R4/DIFFIO_TX_RX_B5N) ; also on sheet 54
FX2_D_N: J8.2(D-) U35.2(D-) U143.9(DMINUS)
FX2_D_P: J8.3(D+) U35.1(D+) U143.8(DPLUS)
FX2_FLAGA: U34.J5(IO_1B_J5/DIFFIO_RX_L20N) U143.29(CTL0)
FX2_FLAGB: U34.H6(IO_1B_H6/DIFFIO_RX_L20P) U143.30(CTL1)
FX2_FLAGC: U34.J3(IO_1B_J3/DIFFIO_RX_L22N) U143.31(CTL2)
FX2_PA0: U34.F5(IO_1A_F5/ADC1IN1/DIFFIO_RX_L1N) U143.33(PA0)
FX2_PA1: U34.C4(IO_1A_C4/ADC2IN1/DIFFIO_RX_L2N) U143.34(PA1)
FX2_PA2: U34.F4(IO_1A_F4/ADC1IN2/DIFFIO_RX_L1P) U143.35(PA2)
FX2_PA3: U34.C3(IO_1A_C3/ADC2IN8/DIFFIO_RX_L2P) U143.36(PA3)
FX2_PA4: U34.H5(IO_1A_H5/ADC1IN3/DIFFIO_RX_L3N) U143.37(PA4)
FX2_PA5: U34.E3(IO_1A_E3/ADC2IN3/DIFFIO_RX_L4N) U143.38(PA5)
FX2_PA6: U34.G5(IO_1A_G5/ADC1IN4/DIFFIO_RX_L3P) U143.39(PA6)
FX2_PA7: U34.F2(IO_1A_F2/ADC2IN4/DIFFIO_RX_L4P) U143.40(PA7)
FX2_PB0: U34.G2(IO_1A_G2/ADC1IN5/DIFFIO_RX_L5N) U143.18(PB0)
FX2_PB1: U34.C2(IO_1A_C2/ADC2IN5/DIFFIO_RX_L6N) U143.19(PB1)
FX2_PB2: U34.F1(IO_1A_F1/ADC1IN6/DIFFIO_RX_L5P) U143.20(PB2)
FX2_PB3: U34.B2(IO_1A_B2/ADC2IN6/DIFFIO_RX_L6P) U143.21(PB3)
FX2_PB4: U34.E1(IO_1A_E1/ADC1IN7/DIFFIO_RX_L7N) U143.22(PB4)
FX2_PB5: U34.B1(IO_1A_B1/ADC2IN7/DIFFIO_RX_L8N) U143.23(PB5)
FX2_PB6: U34.D1(IO_1A_D1/ADC1IN8/DIFFIO_RX_L7P) U143.24(PB6)
FX2_PB7: U34.C1(IO_1A_C1/ADC2IN2/DIFFIO_RX_L8P) U143.25(PB7)
FX2_PD0: U143.45(PD0) ; also on sheet 51
FX2_PD1: U143.46(PD1) ; also on sheet 51
FX2_PD2: U143.47(PD2) ; also on sheet 51
FX2_PD3: U143.48(PD3) ; also on sheet 51
FX2_PD4: U34.T8(IO_3_T8/DIFFIO_RX_B17N) U143.49(PD4)
FX2_PD5: U34.P6(IO_3_P6/DIFFIO_TX_RX_B16P) U143.50(PD5)
FX2_PD6: U34.T6(IO_3) U143.51(PD6)
FX2_PD7: U34.R7(IO_3_R7/DIFFIO_TX_RX_B16N) U143.52(PD7)
FX2_RESETn: R374.1 U33.2(~{RESET}) U34.J2(IO_1B_J2/DIFFIO_RX_L22P) U143.42(~{RESET})
FX2_SCL: R376.1 U34.R8(IO_3_R8/DIFFIO_RX_B17P) U143.15(SCL)
FX2_SDA: R372.1 R377.1 U143.16(SDA)
FX2_SLRDn: U34.R9(IO_3_R9/DIFFIO_RX_B19P) U143.1(RDY0)
FX2_SLWRn: U34.T11(IO_3_T11/DIFFIO_TX_RX_B22N) U143.2(RDY1)
FX2_WAKEUP: C499.1 R381.2 R382.2 R383.2 U143.44(WAKEUP)
G0_EN: R6228.1 U34.E9(IO_8_E9/CLK5N/DIFFIO_RX_T40N)
G1_EN: R6229.1 U34.B3(IO_8_B3/PLL_T_CLKOUTP/DIFFIO_RX_T52P)
G5_EN: R6230.1 U34.L7(IO_3_L7/DIFFIO_TX_RX_B3P)
GXF_PERSTn: R854.1 S5.2 ; also on sheet 28
HPS_JTAG_TCK: U34.J15(IO_6_J15/CLK3P/DIFFIO_RX_R40P) ; also on sheet 36
HPS_JTAG_TDI: U34.H11(IO_6_H11/DIFFIO_RX_R44P/DQ2R) ; also on sheet 36
HPS_JTAG_TDO: U34.H16(IO_6_H16/DIFFIO_RX_R41N) ; also on sheet 36
HPS_JTAG_TMS: U34.G11(IO_6_G11/DPCLK3/DIFFIO_RX_R50P/DQS2R) ; also on sheet 36
HRAM_CK: R6224.2 U103.B2(CK)
HRAM_CK_N: R6225.2 U103.B1(CK#)
HRAM_CK_N_R: R6225.1 U34.L15(IO_5_L15/DIFFIO_RX_R32N/DQSN1R)
HRAM_CK_R: R6224.1 U34.K14(IO_5_K14/DIFFIO_RX_R32P/DQS1R)
HRAM_CS: R2653.2 R6213.2 U103.A3(CS#)
HRAM_CS_R: R6213.1 U34.T15(IO_5_T15/DIFFIO_RX_R2N)
HRAM_D0: R2692.2 U34.P15(IO_5_P15/DIFFIO_RX_R27N/DM1R)
HRAM_D1: R2691.2 U34.N16(IO_5_N16/DIFFIO_RX_R29P)
HRAM_D2: R2693.2 U34.R15(IO_5)
HRAM_D3: R2694.2 U34.P14(IO_5_P14/RUP/DIFFIO_RX_R1P)
HRAM_D4: R2695.2 U34.R14(IO_5_R14/RDN/DIFFIO_RX_R1N)
HRAM_D5: R2696.2 U34.P16(IO_5_P16/DIFFIO_RX_R29N)
HRAM_D6: R2697.2 U34.M15(IO_5_M15/DIFFIO_RX_R28P/DQ1R)
HRAM_D7: R2698.2 U34.M16(IO_5_M16/DIFFIO_RX_R33P/DQ1R)
HRAM_RST_n: R2654.2 U34.T14(IO_5_T14/DIFFIO_RX_R2P) U103.A4(RESET#)
HRAM_RWDS: R6214.2 U103.C3(RWDS)
HRAM_RWDS_R: R6214.1 U34.R16(IO_5_R16/VREFB5N0)
I2C2_SCL: U34.A11(IO_8_A11/DIFFIO_RX_T43P) U107.19(SCL) ; also on sheet 27 32 46 52
I2C2_SDA: U34.B12(IO_8_B12/DIFFIO_RX_T41P) U107.20(SDA) ; also on sheet 27 32 46 52
I2C3_SCL: U34.A12(IO_8_A12/DIFFIO_RX_T43N) ; also on sheet 46
I2C3_SDA: U34.B11(IO_8_B11/DIFFIO_RX_T41N) ; also on sheet 46
IO_1p8V_PG: U34.T3(IO_3_T3/DIFFIO_RX_B6N) ; also on sheet 67
IO_3p3V: R356.2 R359.2 R361.2 R363.2 R364.2 ; also on sheet 25 26 27 30 31 32 43 44 46 47 52 73
IO_EXPNDR1_INT_n: R2742.1 U34.B7(IO_8_B7/DIFFIO_RX_T44N) U107.22(~{INT})
IO_EXPNDR1_RST_n: R2743.1 U34.A6(IO_8_A6/DIFFIO_RX_T47N) U107.24(~{RESET})
JTAG_INPUT_SOURCE: R408.1 SW8.1(A1) U34.B4(IO_8_B4/DIFFIO_RX_T49P)
M10_CONF_DONE: Q15.1(GATE) ; also on sheet 51
M10_GPIO0: U107.12(P12) ; also on sheet 52
M10_GPIO1: U107.13(P13) ; also on sheet 52
MAIN_PMBUS_EN: U34.A15(IO_7_A15/VREFB7N0) ; also on sheet 46
MAX_SDA: R372.2 U34.T9(IO_3_T9/DIFFIO_RX_B19N)
MSEL2_FPGA_nCATTrip: U34.J16(IO_6_J16/CLK3N/DIFFIO_RX_R40N) ; also on sheet 35
OVERTEMPn: D9.C(CATHODE) U107.10(P10)
PCIE_CLK_LOS: U34.M9(IO_3_M9/CLK7P/DIFFIO_TX_RX_B20P) ; also on sheet 44
PCIE_EP_PERSTN: U107.11(P11) ; also on sheet 30 31
PCIE_EP_SMBCLK: U34.B9(IO_8_B9/DIFFIO_RX_T45P) ; also on sheet 30
PCIE_EP_SMBDAT: U34.B5(IO_8_B5/DIFFIO_RX_T48P) ; also on sheet 30
PCIE_PERSTn: R367.1 R369.1 S2.2 ; also on sheet 31
PCIE_PWRBRKN: U107.17(P17) ; also on sheet 30
POWER_ON: R401.1 ; also on sheet 53
POWER_ON_R: R401.2 U34.A2(IO_8_A2/DIFFIO_RX_T51N)
PWR_LED_DR: Q8.1(GATE) R360.1 U107.16(P16)
QSPI_1_M10_CLK: U34.M11(IO_4_M11/PLL_B_CLKOUTN/DIFFIO_TX_RX_B57N) ; also on sheet 35
QSPI_1_M10_CS_N: U34.T13(IO_4_T13/VREFB4N0) ; also on sheet 35
QSPI_1_M10_DATA0: U34.R12(IO_4_R12/DIFFIO_RX_B35P) ; also on sheet 35
QSPI_1_M10_DATA1: U34.T12(IO_4) ; also on sheet 35
QSPI_1_M10_DATA2: U34.P13(IO_4_P13/DIFFIO_TX_RX_B37N) ; also on sheet 35
QSPI_1_M10_DATA3: U34.P12(IO_4_P12/DIFFIO_TX_RX_B37P) ; also on sheet 35
QSPI_1_M10_RESETN: U34.K15(IO_6_K15/DIFFIO_RX_R39N) ; also on sheet 35
QSPI_2_M10_CLK: U34.L10(IO_4_L10/PLL_B_CLKOUTP/DIFFIO_TX_RX_B57P) ; also on sheet 35
QSPI_2_M10_CS_N: U34.P11(IO_4_P11/DIFFIO_TX_RX_B34P) ; also on sheet 35
QSPI_2_M10_DATA0: U34.R11(IO_4_R11/DIFFIO_RX_B35N) ; also on sheet 35
QSPI_2_M10_DATA1: U34.P10(IO_4_P10/DIFFIO_TX_RX_B34N) ; also on sheet 35
QSPI_2_M10_DATA2: U34.M10(IO_4_M10/DIFFIO_TX_RX_B36N) ; also on sheet 35
QSPI_2_M10_DATA3: U34.L9(IO_4_L9/DIFFIO_TX_RX_B36P) ; also on sheet 35
QSPI_2_M10_RESETN: U34.L12(IO_5_L12/DIFFIO_RX_R25N/DQ1R) ; also on sheet 35
QSPI_AVST_SEL: U34.H15(IO_6_H15/DIFFIO_RX_R41P) ; also on sheet 35
SI5391_ENn: U107.1(P00) ; also on sheet 43 44
SI5391_RSTn: U107.6(P05) ; also on sheet 43
STRAP_1_PCLASS1: R2727.2 R2730.2 SW5.2(A2) TP27.1 U34.R6(IO_3_R6/DIFFIO_TX_RX_B13N) ; also on sheet 51
STRAP_2_SMBus_I2C_ADDR: R2721.1 R2726.2 TP28.1 U34.J1(IO_1B_J1/VREFB1N0)
STRAP_3_CVL_PRSNT0_n: R2725.2 R2732.2 SW5.4(A4) ; also on sheet 51
STRAP_4_BRD_REV0: R2635.2 R2637.2 U34.F14(IO_6_F14/DIFFIO_RX_R51P/DQ2R)
STRAP_5_BRD_REV1: R6192.2 R6193.2 U34.E16(IO_6_E16/DIFFIO_RX_R52N/DQ2R)
SW1_3: R2721.2 R2731.2 SW5.3(A3)
SW1_5: R2719.2 R2732.1 SW5.5(B4)
SW1_6: R2718.2 R2731.1 SW5.6(B3) TP25.1
SW1_7: R2717.2 R2730.1 SW5.7(B2) TP24.1
TEMP1_THERMn: U107.7(P06) ; also on sheet 52
TEMP2_THERMn: U107.8(P07) ; also on sheet 52
USB_DISABLEn: U34.T2(IO_3_T2/DIFFIO_RX_B6P) ; also on sheet 51
USB_MAX_JTAGSEL: R413.2 SW8.3(A3) ; also on sheet 51
USB_T_CLK: R378.1 U34.R10(IO_3_R10/DIFFIO_TX_RX_B22P)
N31388806: D7.A(ANODE) R359.1
N31388830: D5.A(ANODE) R356.1
N31388866: D5.C(CATHODE) Q7.3(DRAIN)
N31388880: D7.C(CATHODE) Q9.3(DRAIN)
N31388890: D8.A(ANODE) R361.1
N31388919: D8.C(CATHODE) Q10.3(DRAIN)
N31389008: D10.A(ANODE) R363.1
N31389082: D10.C(CATHODE) Q11.3(DRAIN)
N31389320: D11.A(ANODE) R364.1
N31389364: D11.C(CATHODE) Q12.3(DRAIN)
N33771526: D6.C(CATHODE) Q8.3(DRAIN) R358.2
N33771550: D6.A(ANODE) R357.1
N34054433: D9.A(ANODE) R362.1
N34315909: C491.2 R368.2
N34315982: C492.2 R369.2
N36226098: C493.2 R370.2
N41802473: J9.3(TACH) R414.1
N42584695: C1286.2 R854.2
N46887455: R2692.1 U103.D3(DQ0)
N46887476: R2691.1 U103.D2(DQ1)
N46887502: R2693.1 U103.C4(DQ2)
N46887527: R2694.1 U103.D4(DQ3)
N46887553: R2695.1 U103.D5(DQ4)
N46887581: R2696.1 U103.E3(DQ5)
N46887604: R2697.1 U103.E2(DQ6)
N46887630: R2698.1 U103.E1(DQ7)
N46987350: R2715.2 U107.18(A0)
N46987353: R2716.2 U107.23(A1)
N47015448: D14.C(CATHODE) Q15.3(DRAIN)
N47015450: D14.A(ANODE) R2741.1
N47031477: R384.1 Y4.1(INH)
N47031519: R385.2 Y4.3(OUTPUT)
N49230432: J8.4(ID) R373.2
N49230501: S4.1 U33.3(~{MR})
N49230785: R378.2 U143.13(IFCLK)
N49282986: R412.2 SW8.6(B3)

Not connected (* = marked no-connect by the designer): SW5 1(A1)* 8(B1)*; SW8 4(A4)* 5(B4)*; U34 A10(IO_8)* G12(IO_6_G12/DPCLK2/DIFFIO_RX_R50N/DQSN2R)*; U103 A2(RFU1)* A5(RFU5)* B5(RFU2)* C2(RFU3)* C5(RFU4)*; U143 54(CLKOUT)*

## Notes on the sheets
sheet 48
- LEDs, PushButtons And IO Expander
- I/O EXPANDER
- I2C Address 7-bit 0x74
- POWER LED
sheet 49
- USB Blaster
- 1.8V
- 3.3V
- 3.3V
- IFCLK = 48MHz
- 3.3V
- 1.8V
- 3.3V
- HYPER RAM
- PLACE NEAR CY7C68013A
sheet 50
- 3.3V
- 1.8V
- 3.3V
- 1.8V
- AVST_READY must be double
  registered inside MAX10 for
  syncronization to AVST_CLK
- JTAG Master Selection:
  USB_DISABLEn = 0: External JTAG
  USB_DISABLEn = 1: On-Board UBII/PCIe EP Edge
       JTAG_INPUT_SOURCE = 0: PCIe EP edge
       JTAG_INPUT_SOURCE = 1: On-Board UBII
  JTAG Chain:
  SW5_2 = Low : Bypass
  SW5_2 = High: Enable
- 1.8V
